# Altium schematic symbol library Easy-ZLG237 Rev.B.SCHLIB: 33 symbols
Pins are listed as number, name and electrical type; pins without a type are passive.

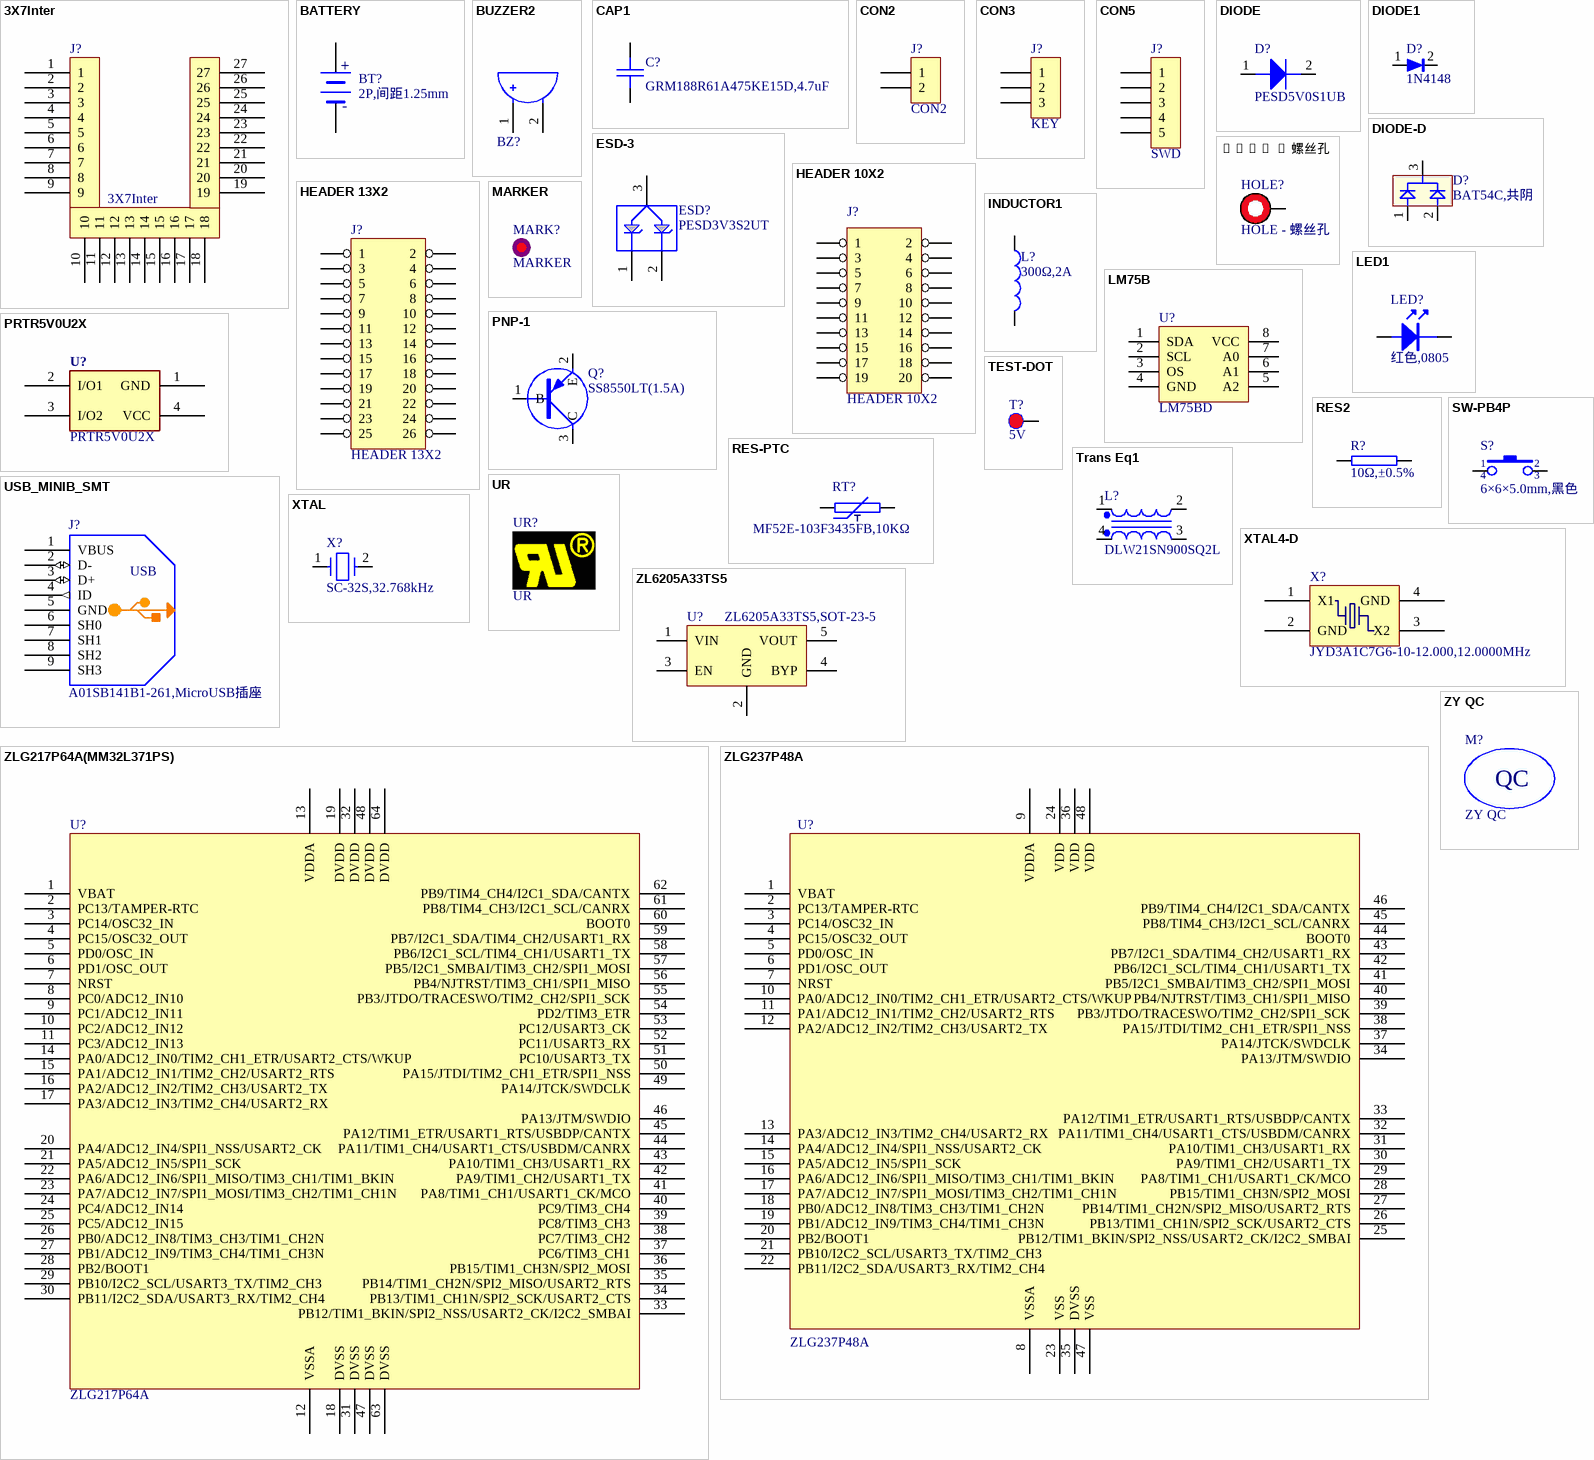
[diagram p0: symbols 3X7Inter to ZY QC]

## 3X7Inter
designator J?
物料代码: 1.10.11.0074
footprint SIP-27 2.54C
footprint SIP-27 2.54C
pins: 1, 2, 3, 4, 5, 6, 7, 8, 9, 10, 11, 12, 13, 14, 15, 16, 17, 18, 19, 20, 21, 22, 23, 24, 25, 26, 27

## BATTERY
designator BT?, comment 2P,间距1.25mm
2P,间距1.25mm,Wafer凹槽边框,90°,WCON; 物料代码: 1.10.05.0281; 名称: 插座; 贴片和直插: SMT; PCB备注: 160927 hcj; 器件优选方案: 正常状态，可以选用
footprint FPC2-49T
pins: 1 +, 2 -
2 alternate drawings of the same symbol

## BUZZER2
designator BZ?  (value not drawn)
Buzzer有极性; 物料代码: 1.06.09.0016; Value: AS-905I-LF,无源; 名称: 讯响器; 厂商: 常州笠翔; 型号: AS-905I-LF,无源,Ф9×4.8mm; 贴片和直插: THT; PCB备注: Flq-Shcj-Twrj-150113; 器件优选方案: 量产物料,优先选用
footprint BUZZ-4/9
pins: 1 A, 2 B
2 alternate drawings of the same symbol

## CAP1
designator C?, comment GRM188R61A475KE15D,4.7uF
GRM188R61A475KE15D,4.7uF,±10%,10V,X5R,0603,muRata,RoHS; 物料代码: 1.02.01.0080; 名称: 电容; 封装: 0603; 贴片和直插: SMT; PCB备注: 160602yjh; 器件优选方案: 正常状态，可以选用
footprint 0603C
pins: 1, 2
2 alternate drawings of the same symbol

## CON2
designator J?
Connector
footprint SIP-2-2.54
pins: 1, 2
2 alternate drawings of the same symbol

## CON3
designator J?, comment KEY
Connector; 物料代码: 1.10.03.0164
footprint SIP-3-2.54
pins: 1, 2, 3
2 alternate drawings of the same symbol

## CON5
designator J?, comment SWD
Connector
footprint SIP-5-2.54-6.0-R90 (引脚伸出部分为6.0mm)
pins: 1, 2, 3, 4, 5
2 alternate drawings of the same symbol

## DIODE
designator D?, comment PESD5V0S1UB
PESD5V0S1UB,SOD-523,Nexperia; 物料代码: 1.04.03.0050; 名称: ESD静电保护器; 贴片和直插: SMT; PCB备注: 180419ZW; 器件优选方案: 正常状态，可以选用
footprint SOD-523
pins: 1, 2
2 alternate drawings of the same symbol

## DIODE1
designator D?  value 1N4148  (hidden comment: DIODE1)
1N4148,SOD-323,RoHS; 物料代码: 1.04.07.0027; 名称: 二极管; 设备封装名称: SOD-323_1N4148; 贴片和直插: SMT
footprint SOD-323
pins: 1, 2
2 alternate drawings of the same symbol

## DIODE-D
designator D?, comment BAT54C,共阴
BAT54C,共阴,200mA,30V,SOT-23-3,NXP,RoHS; 物料代码: 1.04.07.0033; 名称: 二极管; 贴片和直插: SMT; 器件优选方案: 正常状态，可以选用
footprint SOT-23
pins: 1 D1, 2 D2, 3 A

## ESD-3
designator ESD?, comment PESD3V3S2UT
PESD3V3S2UT,SOT-23,NXP,RoHS; 物料代码: 1.05.10.0361; 名称: 集成电路; 设备封装名称: SOT-23_PESD3V3S2UT; 贴片和直插: SMT; 器件优选方案: 量产物料,优先选用
footprint SOT-23
pins: 1, 2, 3
2 alternate drawings of the same symbol

## HEADER 10X2
designator J?
footprint IDC-20-2.54-R90
pins: 1, 2, 3, 4, 5, 6, 7, 8, 9, 10, 11, 12, 13, 14, 15, 16, 17, 18, 19, 20
2 alternate drawings of the same symbol

## HEADER 13X2
designator J?
footprint IDC-26
pins: 1, 2, 3, 4, 5, 6, 7, 8, 9, 10, 11, 12, 13, 14, 15, 16, 17, 18, 19, 20, 21, 22, 23, 24, 25, 26
2 alternate drawings of the same symbol

## HOLE - 螺丝孔
designator HOLE?  (no BOM)
footprint HOLE-2.2  - Screw
footprint HOLE-2.7 - Screw
footprint HOLE-3.2 - Screw
footprint HOLE-3.8 - Screw
pins: 1

## INDUCTOR1
designator L?, comment 300Ω,2A
300Ω,2A,DCR80mΩ,BH05Y354S-300R,SMD,0805,丰晶,RoHS; 物料代码: 1.03.03.0010; 名称: 磁珠; 封装: 0805; 贴片和直插: SMT; 器件优选方案: 正常状态，可以选用
footprint 0805L
pins: 1, 2
2 alternate drawings of the same symbol

## LED1
designator LED?  value 红色,0805  (hidden comment: LED1)
红色,0805,0805,RoHS; 物料代码: 1.04.05.0001; 名称: 发光二极管; 封装: 0805; 设备封装名称: LED0805-RED; 贴片和直插: SMT; 器件优选方案: 样品物料,谨慎选用
footprint LED-0805
footprint LED-0805 (170907内距改0.9mm)
pins: 1, 2
2 alternate drawings of the same symbol

## LM75B
designator U?  value LM75BD  (hidden comment: LM75B)
LM75BD,SO-9,NXP,RoHS; 物料代码: 1.05.10.0602; 名称: IC; 封装: SO-8; 贴片和直插: SMT; 器件优选方案: 样品物料,谨慎选用
footprint SOIC127P600X175-8N
pins: 1 SDA, 2 SCL, 3 OS, 4 GND, 5 A2, 6 A1, 7 A0, 8 VCC
2 alternate drawings of the same symbol

## MARKER
designator MARK?  (no BOM)
footprint MARKER-C-1.0M
footprint MARKER-C-0.8M
footprint MARKER-C-1.0P
pins: 0

## PNP-1
designator Q?  value SS8550LT(1.5A)  (hidden comment: PNP-1)
PNP Transistor; 物料代码: 1.04.09.0002; 名称: 三极管; 封装: SOT-23; 设备封装名称: SOT-23_SS8550LT; 厂商: 江苏长电; 贴片和直插: SMT
footprint SOT-23
pins: 1 B, 2 E, 3 C
2 alternate drawings of the same symbol

## PRTR5V0U2X
designator U?
PRTR5V0U2X,SOT-143B,NXP,RoHS; 物料代码: 1.05.10.0153; 名称: 集成电路; 设备封装名称: SOT-143B_PRTR5V0U2X; 贴片和直插: SMT; 器件优选方案: 量产物料,优先选用
footprint SOT-143
pins: 1 GND, 2 I/O1, 3 I/O2, 4 VCC
2 alternate drawings of the same symbol

## RES2
designator R?, comment 10Ω,±0.5%
10Ω,±0.5%,0402,RoHS; 物料代码: 1.01.17.0049; 名称: 电阻; 封装: 0402; 设备封装名称: R0402_10R_0.5%; 厂商: Ralec; 贴片和直插: SMT; 器件优选方案: 正常状态，可以选用
footprint 0402R
pins: 1, 2
2 alternate drawings of the same symbol

## RES-PTC
designator RT?, comment MF52E-103F3435FB,10KΩ
MF52E-103F3435FB,10KΩ,THT,安培龙; 物料代码: 1.01.14.0023; 名称: 热敏电阻; PCB备注: 180523ZW; 器件优选方案: 正常状态，可以选用
footprint MF52E-103F3435FB
pins: 1, 2

## SW-PB4P
designator S?, comment value 6×6×5.0mm,黑色  (hidden comment: KEY/RES)
6×6×5.0mm,黑色,SMD,,*; 物料代码: 1.09.01.0003; 名称: 轻触按键; 贴片和直插: SMT
footprint KEY-6S
pins: 1, 2, 3, 4
2 alternate drawings of the same symbol

## TEST-DOT
designator T?, comment 5V  (no BOM)
footprint PAD-25/40
footprint PAD-50 (TEST-P)
footprint PAD-25/40
footprint PAD-35/50
footprint TEST
footprint PAD-40
pins: 1

## Trans Eq1
designator L?, comment DLW21SN900SQ2L
DLW21SN900SQ2L,SLN4-0805,村田,RoHS; 物料代码: 1.03.01.0113; 名称: 电感; 厂商: Murata; 贴片和直插: SMT; PCB备注: 181221ZW; 器件优选方案: 正常状态，可以选用
footprint FIL_DLW21S
pins: 1, 2, 3, 4

## UR
designator UR?  (no BOM)
footprint ZY_UR-3X2
footprint ZY_UR-4X3

## USB_MINIB_SMT
designator J?, comment A01SB141B1-261,MicroUSB插座
A01SB141B1-261,MicroUSB插座,SMT,艾立信,RoHS; 物料代码: 1.10.12.0014; PCB备注: 141030lmd; 器件优选方案: 正常状态，可以选用
footprint MICROUSB-5S
pins: 1 VBUS, 2 D- (io), 3 D+ (io), 4 ID (out), 5 GND (power), 6 SH0, 7 SH1, 8 SH2, 9 SH3

## XTAL
designator X?, comment SC-32S,32.768kHz
SC-32S,32.768kHz,12.5pF,±20ppm,SMD3215,SII,RoHS,金属; 物料代码: 1.07.02.0056; 名称: 晶体; 贴片和直插: SMT; 器件优选方案: 正常状态，可以选用
footprint XTAL320X150X90
pins: 1, 2

## XTAL4-D
designator X?, comment JYD3A1C7G6-10-12.000,12.0000MHz
JYD3A1C7G6-10-12.000,12.0000MHz,±10ppm,10pF,-40~85℃,±10ppm,SMD3225,*,JYEG,RoHS; 物料代码: 1.07.01.0032; 名称: 晶体; 贴片和直插: SMT; PCB备注: 151229lmd171128ZW; 器件优选方案: 正常状态，可以选用
footprint OSCCC250X320X80-4N
pins: 1 X1, 2 GND, 3 X2, 4 GND

## ZL6205A33TS5
designator U?, comment ZL6205A33TS5,SOT-23-5
ZL6205A33TS5,SOT-23-5,ZLG; 物料代码: 08.09.03069; 名称: 集成电路; 贴片和直插: SMT; PCB备注: 190806hcj; 器件优选方案: 待导入物料
footprint SOT-23-5
pins: 1 VIN, 2 GND, 3 EN, 4 BYP, 5 VOUT

## ZLG217P64A(MM32L371PS)
designator U?, comment ZLG217P64A
ZLG217P64A,LQFP64,ZLG; 物料代码: 1.05.02.0207; 名称: 集成电路; 贴片和直插: SMT; PCB备注: 171017lmd; 器件优选方案: 正常状态，可以选用
footprint QFP50P1200X1200X160-64N
footprint QFP50P1200X1200X160-64L
pins: 1 VBAT (power), 2 PC13/TAMPER-RTC, 3 PC14/OSC32_IN, 4 PC15/OSC32_OUT, 5 PD0/OSC_IN (power), 6 PD1/OSC_OUT, 7 NRST, 8 PC0/ADC12_IN10, 9 PC1/ADC12_IN11, 10 PC2/ADC12_IN12, 11 PC3/ADC12_IN13, 12 VSSA, 13 VDDA, 14 PA0/ADC12_IN0/TIM2_CH1_ETR/USART2_CTS/WKUP, 15 PA1/ADC12_IN1/TIM2_CH2/USART2_RTS, 16 PA2/ADC12_IN2/TIM2_CH3/USART2_TX, 17 PA3/ADC12_IN3/TIM2_CH4/USART2_RX, 18 DVSS, 19 DVDD, 20 PA4/ADC12_IN4/SPI1_NSS/USART2_CK, 21 PA5/ADC12_IN5/SPI1_SCK, 22 PA6/ADC12_IN6/SPI1_MISO/TIM3_CH1/TIM1_BKIN, 23 PA7/ADC12_IN7/SPI1_MOSI/TIM3_CH2/TIM1_CH1N, 24 PC4/ADC12_IN14, 25 PC5/ADC12_IN15, 26 PB0/ADC12_IN8/TIM3_CH3/TIM1_CH2N, 27 PB1/ADC12_IN9/TIM3_CH4/TIM1_CH3N, 28 PB2/BOOT1, 29 PB10/I2C2_SCL/USART3_TX/TIM2_CH3, 30 PB11/I2C2_SDA/USART3_RX/TIM2_CH4, 31 DVSS, 32 DVDD, 33 PB12/TIM1_BKIN/SPI2_NSS/USART2_CK/I2C2_SMBAI, 34 PB13/TIM1_CH1N/SPI2_SCK/USART2_CTS, 35 PB14/TIM1_CH2N/SPI2_MISO/USART2_RTS, 36 PB15/TIM1_CH3N/SPI2_MOSI, 37 PC6/TIM3_CH1, 38 PC7/TIM3_CH2, 39 PC8/TIM3_CH3, 40 PC9/TIM3_CH4, 41 PA8/TIM1_CH1/USART1_CK/MCO, 42 PA9/TIM1_CH2/USART1_TX, 43 PA10/TIM1_CH3/USART1_RX, 44 PA11/TIM1_CH4/USART1_CTS/USBDM/CANRX, 45 PA12/TIM1_ETR/USART1_RTS/USBDP/CANTX, 46 PA13/JTM/SWDIO, 47 DVSS, 48 DVDD, 49 PA14/JTCK/SWDCLK, 50 PA15/JTDI/TIM2_CH1_ETR/SPI1_NSS, 51 PC10/USART3_TX, 52 PC11/USART3_RX, 53 PC12/USART3_CK, 54 PD2/TIM3_ETR, 55 PB3/JTDO/TRACESWO/TIM2_CH2/SPI1_SCK, 56 PB4/NJTRST/TIM3_CH1/SPI1_MISO, 57 PB5/I2C1_SMBAI/TIM3_CH2/SPI1_MOSI, 58 PB6/I2C1_SCL/TIM4_CH1/USART1_TX, 59 PB7/I2C1_SDA/TIM4_CH2/USART1_RX, 60 BOOT0, 61 PB8/TIM4_CH3/I2C1_SCL/CANRX, 62 PB9/TIM4_CH4/I2C1_SDA/CANTX, 63 DVSS, 64 DVDD

## ZLG237P48A
designator U?
footprint QFP50P900X900X160-48L
pins: 1 VBAT (power), 2 PC13/TAMPER-RTC, 3 PC14/OSC32_IN, 4 PC15/OSC32_OUT, 5 PD0/OSC_IN (power), 6 PD1/OSC_OUT, 7 NRST, 8 VSSA, 9 VDDA, 10 PA0/ADC12_IN0/TIM2_CH1_ETR/USART2_CTS/WKUP, 11 PA1/ADC12_IN1/TIM2_CH2/USART2_RTS, 12 PA2/ADC12_IN2/TIM2_CH3/USART2_TX, 13 PA3/ADC12_IN3/TIM2_CH4/USART2_RX, 14 PA4/ADC12_IN4/SPI1_NSS/USART2_CK, 15 PA5/ADC12_IN5/SPI1_SCK, 16 PA6/ADC12_IN6/SPI1_MISO/TIM3_CH1/TIM1_BKIN, 17 PA7/ADC12_IN7/SPI1_MOSI/TIM3_CH2/TIM1_CH1N, 18 PB0/ADC12_IN8/TIM3_CH3/TIM1_CH2N, 19 PB1/ADC12_IN9/TIM3_CH4/TIM1_CH3N, 20 PB2/BOOT1, 21 PB10/I2C2_SCL/USART3_TX/TIM2_CH3, 22 PB11/I2C2_SDA/USART3_RX/TIM2_CH4, 23 VSS, 24 VDD, 25 PB12/TIM1_BKIN/SPI2_NSS/USART2_CK/I2C2_SMBAI, 26 PB13/TIM1_CH1N/SPI2_SCK/USART2_CTS, 27 PB14/TIM1_CH2N/SPI2_MISO/USART2_RTS, 28 PB15/TIM1_CH3N/SPI2_MOSI, 29 PA8/TIM1_CH1/USART1_CK/MCO, 30 PA9/TIM1_CH2/USART1_TX, 31 PA10/TIM1_CH3/USART1_RX, 32 PA11/TIM1_CH4/USART1_CTS/USBDM/CANRX, 33 PA12/TIM1_ETR/USART1_RTS/USBDP/CANTX, 34 PA13/JTM/SWDIO, 35 DVSS, 36 VDD, 37 PA14/JTCK/SWDCLK, 38 PA15/JTDI/TIM2_CH1_ETR/SPI1_NSS, 39 PB3/JTDO/TRACESWO/TIM2_CH2/SPI1_SCK, 40 PB4/NJTRST/TIM3_CH1/SPI1_MISO, 41 PB5/I2C1_SMBAI/TIM3_CH2/SPI1_MOSI, 42 PB6/I2C1_SCL/TIM4_CH1/USART1_TX, 43 PB7/I2C1_SDA/TIM4_CH2/USART1_RX, 44 BOOT0, 45 PB8/TIM4_CH3/I2C1_SCL/CANRX, 46 PB9/TIM4_CH4/I2C1_SDA/CANTX, 47 VSS, 48 VDD

## ZY QC
designator M?  (no BOM)
footprint ZY_QC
